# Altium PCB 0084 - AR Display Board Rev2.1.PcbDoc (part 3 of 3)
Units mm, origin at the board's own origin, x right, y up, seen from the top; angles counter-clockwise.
Board outline 127.7 x 27.2 mm, 4 copper layers (L1-TOP, L2-GND, L3-GND, L4-BOT), stack 1.571 mm thick; 141 components, 141 nets, 671 pads, 447 vias.
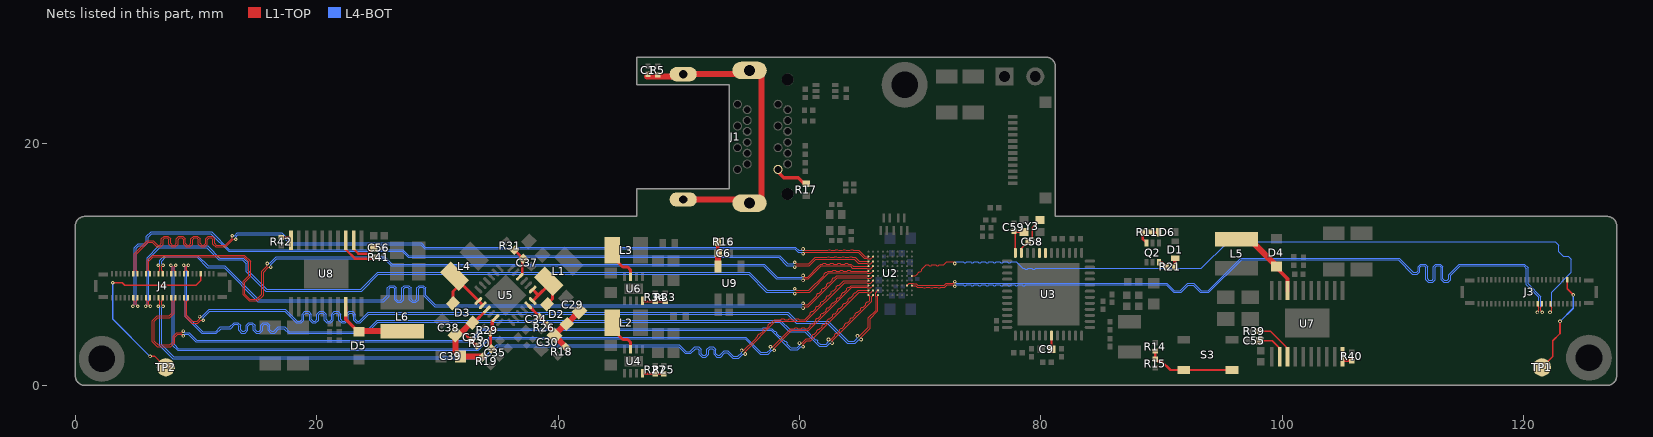
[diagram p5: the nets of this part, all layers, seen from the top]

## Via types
v1: diameter 0.3, hole 0.15, L1-TOP to L4-BOT, tented both sides, 445 vias
v2: diameter 0.25, hole 0.1, L1-TOP to L4-BOT, tented both sides, 2 vias

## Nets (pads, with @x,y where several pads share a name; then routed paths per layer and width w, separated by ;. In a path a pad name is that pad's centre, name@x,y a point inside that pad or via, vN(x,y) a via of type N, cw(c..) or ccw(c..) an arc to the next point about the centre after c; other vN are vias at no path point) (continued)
MIPI_DSI01_3_P: J3.35 U2.F10 | length 63.9
  L1-TOP w0.076: U2.F10@69.3,9.075 69.591,9.075 69.698,9.183 69.914,9.398 70.022,9.398 70.129,9.506 70.129,9.614 70.345,9.829 70.516,10 70.668,10 70.744,9.924 70.897,9.924 70.973,10 71.278,10 71.354,9.924 71.506,9.924 71.582,10 71.8,10 71.96,10 72.184,10.224 72.736,10.224 v1(72.86,10.1) ; v1@122.187,6.05 v1(122.175,6.05) 122.299,6.174 122.299,6.476 122.2,6.575 J3.35@122.2,6.75
  L4-BOT w0.076: v1(72.86,10.1) 72.984,10.224 73.1,10.224 73.252,10.224 73.557,10.224 73.633,10.148 73.786,10.148 73.862,10.224 74.167,10.224 74.243,10.148 74.395,10.148 74.472,10.224 74.776,10.224 74.853,10.148 75.005,10.148 75.081,10.224 75.386,10.224 75.462,10.148 75.615,10.148 75.691,10.224 75.996,10.224 76.072,10.148 76.224,10.148 76.3,10.224 76.605,10.224 76.681,10.148 76.834,10.148 76.91,10.224 77.215,10.224 77.291,10.148 77.443,10.148 77.52,10.224 77.824,10.224 77.961,10.224 78.484,9.7 78.637,9.7 78.713,9.624 78.865,9.624 78.942,9.7 79.246,9.7 79.323,9.624 79.475,9.624 79.551,9.7 79.6,9.7 93.3,9.7 95.5,11.9 122.6,11.9 122.9,11.6 122.9,11.084 123.284,10.7 123.684,10.7 123.948,10.437 123.948,9.376 122.299,7.727 122.299,6.174 v1(122.175,6.05)
MIPI_DSI01_C_N: J3.31 U2.H9 | length 64
  L1-TOP w0.076: U2.H9@68.9,8.275 69.1,8.475 69.383,8.475 69.43,8.427 69.673,8.427 69.8,8.3 71.984,8.3 72.161,8.476 72.736,8.476 v1(72.86,8.6) ; J3.31@121.5,6.75 121.5,6.575 121.401,6.476 121.401,6.174 v1(121.525,6.05) v1@121.513,6.05
  L4-BOT w0.076: v1(72.86,8.6) 72.984,8.476 90.439,8.476 91.063,7.852 91.552,7.852 92.152,8.452 92.663,8.452 93.263,7.852 93.852,7.852 96.552,10.552 109.663,10.552 ; 109.678,10.552 109.663,10.552 ; v1(121.525,6.05) 121.401,6.174 121.401,7.35 120.351,8.4 120.351,9.739 120.041,10.05 114.657,10.05 113.781,9.174 113.781,8.824 113.667,8.71 113.413,8.71 113.299,8.824 113.299,9.841 113.095,10.045 112.715,10.045 112.511,9.841 112.511,8.824 112.397,8.71 112.143,8.71 112.029,8.824 112.029,9.841 111.825,10.045 111.445,10.045 111.241,9.841 111.241,9.492 111.127,9.377 110.838,9.377 109.663,10.552
MIPI_DSI01_C_P: J3.29 U2.H10 | length 63.9
  L1-TOP w0.076: U2.H10@69.3,8.275 69.609,8.275 69.737,8.148 69.889,8.148 70.194,8.148 70.27,8.071 70.423,8.071 70.499,8.148 70.804,8.148 70.88,8.071 71.032,8.071 71.108,8.148 71.413,8.148 71.489,8.071 71.642,8.071 71.718,8.148 72.023,8.148 72.048,8.148 72.224,8.324 72.736,8.324 v1(72.86,8.2) ; v1@121.137,6.05 v1(121.125,6.05) 121.249,6.174 121.249,6.476 121.15,6.575 J3.29@121.15,6.75
  L4-BOT w0.076: v1(72.86,8.2) 72.984,8.324 73.1,8.324 73.252,8.324 73.557,8.324 73.633,8.248 73.786,8.248 73.862,8.324 74.167,8.324 74.243,8.248 74.395,8.248 74.472,8.324 74.776,8.324 74.853,8.248 75.005,8.248 75.081,8.324 75.386,8.324 75.462,8.248 75.615,8.248 75.691,8.324 75.996,8.324 76.072,8.248 76.224,8.248 76.3,8.324 76.605,8.324 76.681,8.248 76.834,8.248 76.91,8.324 77.215,8.324 77.291,8.248 77.443,8.248 77.52,8.324 77.824,8.324 77.901,8.248 78.053,8.248 78.129,8.324 78.434,8.324 78.51,8.248 78.663,8.248 78.739,8.324 90.376,8.324 91,7.7 91.616,7.7 92.216,8.3 92.6,8.3 93.2,7.7 93.916,7.7 96.616,10.4 109.6,10.4 110.775,9.225 111.19,9.225 111.394,9.428 111.394,9.778 111.508,9.892 111.762,9.892 111.876,9.778 111.876,8.761 112.08,8.558 112.46,8.558 112.664,8.761 112.664,9.778 112.778,9.892 113.032,9.892 113.146,9.778 113.146,8.761 113.35,8.558 113.73,8.558 113.934,8.761 113.934,9.111 114.72,9.898 119.977,9.898 120.199,9.676 120.199,8.337 121.249,7.287 121.249,6.174 v1(121.125,6.05)
MIPI_DSI10_0_N: J4.11 U2.C1 | length 69.1
  L1-TOP w0.076: v1@4.787,6.55 v1(4.775,6.55) 4.899,6.674 4.899,6.976 4.8,7.075 J4.11@4.8,7.25 ; v1(59.6,10.2) 59.724,10.076 60.761,10.076 61.284,10.6 62.1,10.6 62.252,10.6 62.329,10.676 62.481,10.676 62.557,10.6 62.862,10.6 62.938,10.676 63.091,10.676 63.167,10.6 63.472,10.6 63.548,10.676 63.7,10.676 63.776,10.6 64.081,10.6 64.157,10.676 64.31,10.676 64.386,10.6 64.616,10.6 64.941,10.275 U2.C1@65.7,10.275
  L4-BOT w0.076: v1(4.775,6.55) 4.899,6.674 4.899,11.414 5.212,11.727 5.712,11.727 5.898,11.913 5.898,12.338 6.287,12.727 11.288,12.727 12.763,11.252 27.138,11.252 27.638,10.752 58.348,10.752 59.024,10.076 59.476,10.076 v1(59.6,10.2)
MIPI_DSI10_0_P: J4.13 U2.C2 | length 69.1
  L1-TOP w0.076: J4.13@5.15,7.25 5.15,7.075 5.051,6.976 5.051,6.674 v1(5.175,6.55) v1@5.163,6.55 ; v1(59.6,9.8) 59.724,9.924 60.824,9.924 61.348,10.448 64.552,10.448 64.877,10.123 65.57,10.123 65.617,10.075 65.9,10.075 U2.C2@66.1,10.275
  L4-BOT w0.076: v1(5.175,6.55) 5.051,6.674 5.051,11.351 5.275,11.575 5.775,11.575 6.05,11.85 6.05,12.275 6.35,12.575 11.225,12.575 12.7,11.1 27.075,11.1 27.575,10.6 58.284,10.6 58.961,9.924 59.476,9.924 v1(59.6,9.8)
MIPI_DSI10_1_N: J4.17 U2.E1 | length 69.1
  L1-TOP w0.076: v1@5.837,6.55 v1(5.825,6.55) 5.949,6.674 5.949,6.976 5.85,7.075 J4.17@5.85,7.25 ; v1(59.6,8) 59.724,7.876 60.776,7.876 62,9.1 62.052,9.152 62.052,9.259 62.159,9.367 62.267,9.367 62.375,9.475 62.414,9.475 62.719,9.475 62.795,9.551 62.947,9.551 63.024,9.475 63.328,9.475 63.405,9.551 63.557,9.551 63.633,9.475 63.938,9.475 64.014,9.551 64.167,9.551 64.243,9.475 64.548,9.475 64.7,9.475 U2.E1@65.7,9.475
  L4-BOT w0.076: v1(5.825,6.55) 5.949,6.674 5.949,10.564 6.937,11.552 10.963,11.552 11.963,10.552 13.913,10.552 14.325,10.141 14.325,9.491 15.863,7.952 23.652,7.952 25.052,9.352 55.848,9.352 57.324,7.876 59.476,7.876 v1(59.6,8)
MIPI_DSI10_1_P: J4.19 U2.E2 | length 69.1
  L1-TOP w0.076: J4.19@6.2,7.25 6.2,7.075 6.101,6.976 6.101,6.674 v1(6.225,6.55) v1@6.213,6.55 ; v1(59.6,7.6) 59.724,7.724 60.839,7.724 62.438,9.323 65.57,9.323 65.617,9.275 65.9,9.275 U2.E2@66.1,9.475
  L4-BOT w0.076: v1(6.225,6.55) 6.101,6.674 6.101,10.501 7,11.4 10.9,11.4 11.9,10.4 13.85,10.4 14.173,10.077 14.173,9.427 15.8,7.8 23.716,7.8 25.116,9.2 55.784,9.2 57.261,7.724 59.476,7.724 v1(59.6,7.6)
MIPI_DSI10_2_N: J4.24 U2.F1 | length 69.1
  L1-TOP w0.076: v1@6.887,9.95 v1(6.875,9.95) 6.999,9.826 6.999,9.524 6.9,9.425 J4.24@6.9,9.25 ; v1(60.3,6.8) 60.424,6.676 60.676,6.676 61.3,7.3 61.408,7.408 61.408,7.516 61.516,7.623 61.623,7.623 61.839,7.839 61.839,7.947 61.947,8.054 62.054,8.054 62.27,8.27 62.27,8.378 62.378,8.485 62.485,8.485 62.701,8.701 62.701,8.809 62.809,8.916 62.916,8.916 63,9 63.075,9.075 U2.F1@65.7,9.075
  L4-BOT w0.076: v1(6.875,9.95) 6.999,10.074 6.999,10.363 7.436,10.8 10.116,10.8 11.016,9.9 12.4,9.9 15.2,7.1 25.485,7.1 25.848,7.462 25.848,8.073 26.049,8.275 26.408,8.275 26.61,8.073 26.61,7.14 26.725,7.025 26.933,7.025 27.067,7.159 27.067,8.073 27.269,8.275 27.627,8.275 27.829,8.073 27.829,7.167 27.971,7.025 28.152,7.025 28.286,7.159 28.286,8.073 28.488,8.275 28.847,8.275 29.048,8.073 29.048,7.462 29.834,6.676 60.176,6.676 v1(60.3,6.8)
MIPI_DSI10_2_P: J4.26 U2.F2 | length 69.1
  L1-TOP w0.076: J4.26@7.25,9.25 7.25,9.425 7.151,9.524 7.151,9.826 v1(7.275,9.95) v1@7.263,9.95 ; v1(60.3,6.4) 60.424,6.524 60.739,6.524 63.138,8.923 65.57,8.923 65.617,8.875 65.9,8.875 U2.F2@66.1,9.075
  L4-BOT w0.076: v1(7.275,9.95) 7.151,10.074 7.151,10.3 7.499,10.648 10.052,10.648 10.952,9.748 12.337,9.748 15.137,6.948 25.549,6.948 26,7.399 26,8.01 26.113,8.123 26.345,8.123 26.457,8.01 26.457,7.077 26.662,6.872 26.996,6.872 27.219,7.096 27.219,8.01 27.332,8.123 27.564,8.123 27.677,8.01 27.677,7.104 27.908,6.872 28.215,6.872 28.439,7.096 28.439,8.01 28.551,8.123 28.783,8.123 28.896,8.01 28.896,7.399 29.771,6.524 60.176,6.524 v1(60.3,6.4)
MIPI_DSI10_3_N: J4.12 U2.B1 | length 69.1
  L1-TOP w0.076: J4.12@4.8,9.25 4.8,9.425 4.899,9.524 4.899,10.914 5.984,12 6.447,12 6.823,11.624 7.004,11.624 7.142,11.762 7.142,12.148 7.37,12.376 7.677,12.376 7.904,12.148 7.904,11.762 8.042,11.624 8.223,11.624 8.361,11.762 8.361,12.148 8.589,12.376 8.896,12.376 9.123,12.148 9.123,11.762 9.262,11.624 9.442,11.624 9.581,11.762 9.581,12.148 9.808,12.376 10.115,12.376 10.343,12.148 10.343,11.762 10.481,11.624 10.662,11.624 10.8,11.762 10.8,12.148 11.027,12.376 11.334,12.376 11.562,12.148 11.562,11.762 11.7,11.624 12.416,11.624 13,12.208 v1(13,12.4) ; v1(60.3,11.3) 60.424,11.176 62.1,11.176 62.333,11.176 62.409,11.252 62.562,11.252 62.638,11.176 62.943,11.176 63.019,11.252 63.171,11.252 63.247,11.176 63.552,11.176 63.628,11.252 63.781,11.252 63.857,11.176 64.162,11.176 64.238,11.252 64.39,11.252 64.467,11.176 64.771,11.176 64.924,11.176 65.425,10.675 U2.B1@65.7,10.675
  L4-BOT w0.076: v1(13,12.4) 13.192,12.4 13.417,12.625 17.091,12.625 17.916,11.8 28.666,11.8 29.013,11.452 59.663,11.452 59.939,11.176 60.176,11.176 v1(60.3,11.3)
MIPI_DSI10_3_P: J4.14 U2.B2 | length 69.1
  L1-TOP w0.076: J4.14@5.15,9.25 5.15,9.425 5.051,9.524 5.051,10.851 6.048,11.848 6.384,11.848 6.76,11.472 7.067,11.472 7.295,11.699 7.295,12.085 7.433,12.224 7.614,12.224 7.752,12.085 7.752,11.699 7.979,11.472 8.286,11.472 8.514,11.699 8.514,12.085 8.652,12.224 8.833,12.224 8.971,12.085 8.971,11.699 9.199,11.472 9.505,11.472 9.733,11.699 9.733,12.085 9.871,12.224 10.052,12.224 10.19,12.085 10.19,11.699 10.418,11.472 10.725,11.472 10.952,11.699 10.952,12.085 11.09,12.224 11.271,12.224 11.409,12.085 11.409,11.699 11.637,11.472 12.479,11.472 13.108,12.1 v1(13.3,12.1) ; v1(60.3,10.9) 60.424,11.024 64.861,11.024 65.362,10.523 65.57,10.523 65.617,10.475 65.9,10.475 U2.B2@66.1,10.675
  L4-BOT w0.076: v1(13.3,12.1) 13.3,12.292 13.48,12.473 17.027,12.473 17.852,11.648 28.602,11.648 28.95,11.3 59.6,11.3 59.876,11.024 60.176,11.024 v1(60.3,10.9)
MIPI_DSI10_C_N: J4.18 U2.D1 | length 69.1
  L1-TOP w0.076: J4.18@5.85,9.25 5.85,9.425 5.949,9.524 5.949,10.349 6.4,10.8 14.016,10.8 14.525,10.291 14.525,9.025 14.052,8.552 14.052,7.563 14.463,7.152 15.052,7.152 15.448,7.548 15.448,9.455 15.9,9.908 v1(15.9,10.1) ; v1(60.3,9.1) 60.424,8.976 60.676,8.976 61.6,9.9 61.708,10.008 61.752,10.052 61.905,10.052 61.981,10.129 62.133,10.129 62.21,10.052 62.514,10.052 62.591,10.129 62.743,10.129 62.819,10.052 63.124,10.052 63.2,10.129 63.353,10.129 63.429,10.052 63.734,10.052 63.81,10.129 63.962,10.129 64.038,10.052 64.2,10.052 64.263,10.052 64.441,9.875 U2.D1@65.7,9.875
  L4-BOT w0.076: v1(15.9,10.1) 16.092,10.1 16.645,10.652 25.648,10.652 26.248,10.052 57.063,10.052 58.139,8.976 60.176,8.976 v1(60.3,9.1)
MIPI_DSI10_C_P: J4.20 U2.D2 | length 69.1
  L1-TOP w0.076: J4.20@6.2,9.25 6.2,9.425 6.101,9.524 6.101,10.286 6.463,10.648 13.952,10.648 14.373,10.227 14.373,9.088 13.9,8.616 13.9,7.5 14.4,7 15.116,7 15.6,7.484 15.6,9.392 16.008,9.8 v1(16.2,9.8) ; v1(60.3,8.7) 60.424,8.824 60.739,8.824 61.816,9.9 64.2,9.9 64.377,9.723 65.57,9.723 65.617,9.675 65.9,9.675 U2.D2@66.1,9.875
  L4-BOT w0.076: v1(16.2,9.8) 16.2,9.992 16.708,10.5 25.584,10.5 26.184,9.9 57,9.9 58.076,8.824 60.176,8.824 v1(60.3,8.7)
MIPI_DSI11_0_N: J4.38 U2.K1 | length 69.1
  L1-TOP w0.076: J4.38@9.35,9.25 9.35,9.425 9.251,9.524 9.251,9.826 v1(9.375,9.95) v1@9.363,9.95 ; v1(62.4,3.8) 62.592,3.8 62.792,4 62.9,4.108 62.9,4.216 63.008,4.323 63.116,4.323 63.331,4.539 63.331,4.647 63.439,4.754 63.547,4.754 63.762,4.97 63.762,5.078 63.87,5.185 63.978,5.185 64.193,5.401 64.193,5.509 64.301,5.616 64.409,5.616 64.624,5.832 64.624,5.94 64.732,6.047 64.84,6.047 65.055,6.263 65.055,6.371 65.163,6.479 65.271,6.479 65.486,6.694 65.486,6.802 65.594,6.91 65.702,6.91 65.8,7.008 65.824,7.032 65.824,7.351 U2.K1@65.7,7.475
  L4-BOT w0.076: v1(9.375,9.95) 9.251,9.826 9.251,5.749 10.548,4.452 11.637,4.452 12.029,4.845 12.8,4.845 13.156,5.201 13.463,5.201 13.691,4.973 13.691,4.627 13.829,4.488 14.01,4.488 14.148,4.627 14.148,4.973 14.375,5.201 14.682,5.201 14.91,4.973 14.91,4.627 15.048,4.488 15.229,4.488 15.367,4.627 15.367,4.973 15.595,5.201 15.901,5.201 16.129,4.973 16.129,4.627 16.267,4.488 16.448,4.488 16.804,4.845 17.355,4.845 17.748,4.452 24.052,4.452 25,5.4 58.416,5.4 59.216,4.6 60.5,4.6 61.308,3.792 61.416,3.792 61.523,3.684 61.523,3.577 61.696,3.404 62.196,3.404 62.4,3.608 v1(62.4,3.8)
MIPI_DSI11_0_P: J4.36 U2.K2 | length 69.1
  L1-TOP w0.076: v1@8.987,9.95 v1(8.975,9.95) 9.099,9.826 9.099,9.524 9,9.425 J4.36@9,9.25 ; v1(62.7,3.5) 62.7,3.692 65.976,6.968 65.976,7.351 U2.K2@66.1,7.475
  L4-BOT w0.076: v1(8.975,9.95) 9.099,9.826 9.099,5.686 10.484,4.3 11.7,4.3 12.092,4.692 12.863,4.692 13.219,5.049 13.4,5.049 13.538,4.91 13.538,4.563 13.766,4.336 14.073,4.336 14.3,4.563 14.3,4.91 14.438,5.049 14.619,5.049 14.757,4.91 14.757,4.563 14.985,4.336 15.292,4.336 15.519,4.563 15.519,4.91 15.658,5.049 15.838,5.049 15.977,4.91 15.977,4.563 16.204,4.336 16.511,4.336 16.867,4.692 17.292,4.692 17.684,4.3 24.116,4.3 25.063,5.248 58.352,5.248 59.152,4.448 60.437,4.448 61.633,3.251 62.259,3.251 62.508,3.5 v1(62.7,3.5)
MIPI_DSI11_1_N: J4.32 U2.H1 | length 69.1
  L1-TOP w0.076: J4.32@8.3,9.25 8.3,9.425 8.201,9.524 8.201,9.826 v1(8.325,9.95) v1@8.313,9.95 ; v1(57.6,3.2) 57.792,3.2 59.292,4.7 59.4,4.7 59.552,4.7 59.629,4.776 59.781,4.776 59.857,4.7 60.162,4.7 60.238,4.776 60.391,4.776 60.467,4.7 60.6,4.7 60.7,4.7 60.8,4.8 60.908,4.908 60.908,5.016 61.016,5.123 61.123,5.123 61.339,5.339 61.339,5.447 61.447,5.554 61.554,5.554 61.77,5.77 61.77,5.878 61.878,5.985 61.985,5.985 62.201,6.201 62.201,6.309 62.309,6.416 62.416,6.416 62.632,6.632 62.632,6.74 62.74,6.847 62.847,6.847 63.063,7.063 63.063,7.171 63.171,7.279 63.279,7.279 63.494,7.494 63.494,7.602 63.602,7.71 63.71,7.71 63.925,7.925 63.925,8.033 64.033,8.141 64.141,8.141 64.275,8.275 64.427,8.275 ; 64.3,8.275 64.427,8.275 ; U2.H1@65.7,8.275 64.427,8.275
  L4-BOT w0.076: v1(8.325,9.95) 8.201,9.826 8.201,9.537 8.2,9.536 8.2,3.4 8.548,3.052 33.337,3.052 34.284,4 55.55,4 56.8,2.75 57.342,2.75 57.6,3.008 v1(57.6,3.2)
MIPI_DSI11_1_P: J4.30 U2.H2 | length 69.1
  L1-TOP w0.076: v1@7.937,9.95 v1(7.925,9.95) 8.049,9.826 8.049,9.524 7.95,9.425 J4.30@7.95,9.25 ; v1(57.9,2.9) 57.9,3.092 59.355,4.548 60.763,4.548 64.338,8.123 65.57,8.123 65.617,8.075 65.9,8.075 U2.H2@66.1,8.275
  L4-BOT w0.076: v1(7.925,9.95) 8.049,9.826 8.049,9.6 8.048,9.599 8.048,3.337 8.484,2.9 33.4,2.9 34.348,3.848 55.487,3.848 56.737,2.598 57.405,2.598 57.708,2.9 v1(57.9,2.9)
MIPI_DSI11_2_N: J4.25 U2.G1 | length 69.1
  L1-TOP w0.076: J4.25@7.25,7.25 7.25,7.075 7.151,6.976 7.151,6.674 v1(7.275,6.55) v1@7.263,6.55 ; v1(55.2,2.9) 55.392,2.9 56.292,3.8 56.544,4.051 56.544,4.159 56.651,4.267 56.759,4.267 56.975,4.483 56.975,4.59 57.083,4.698 57.19,4.698 57.406,4.914 57.406,5.021 57.514,5.129 57.621,5.129 57.837,5.345 57.945,5.452 58.3,5.452 58.452,5.452 58.529,5.529 58.681,5.529 58.757,5.452 59.062,5.452 59.138,5.529 59.291,5.529 59.367,5.452 59.672,5.452 59.748,5.529 59.9,5.529 59.976,5.452 60.2,5.452 60.452,5.452 60.7,5.7 60.906,5.906 60.906,6.014 61.014,6.121 61.121,6.121 61.337,6.337 61.337,6.445 61.445,6.552 61.553,6.552 61.768,6.768 61.768,6.876 61.876,6.984 61.984,6.984 62.199,7.199 62.199,7.307 62.307,7.415 62.415,7.415 62.63,7.63 62.63,7.738 62.738,7.846 62.846,7.846 63.061,8.061 63.061,8.169 63.169,8.277 63.277,8.277 63.492,8.492 63.6,8.6 63.675,8.675 U2.G1@65.7,8.675
  L4-BOT w0.076: v1(7.275,6.55) 7.151,6.426 7.151,3.349 8.148,2.352 33.937,2.352 34.937,3.352 50.048,3.352 50.6,2.8 50.918,2.8 51.325,3.207 51.632,3.207 51.86,2.979 51.86,2.636 51.998,2.498 52.179,2.498 52.317,2.636 52.317,2.979 52.545,3.207 52.852,3.207 53.079,2.979 53.079,2.636 53.217,2.498 53.398,2.498 53.753,2.852 54.063,2.852 54.516,2.4 54.892,2.4 55.2,2.708 v1(55.2,2.9)
MIPI_DSI11_2_P: J4.23 U2.G2 | length 69.1
  L1-TOP w0.076: v1@6.887,6.55 v1(6.875,6.55) 6.999,6.674 6.999,6.976 6.9,7.075 J4.23@6.9,7.25 ; v1(55.5,2.6) 55.5,2.792 58.008,5.3 60.516,5.3 63.738,8.523 65.57,8.523 65.617,8.475 65.9,8.475 U2.G2@66.1,8.675
  L4-BOT w0.076: v1(6.875,6.55) 6.999,6.426 6.999,3.286 8.084,2.2 34,2.2 35,3.2 49.984,3.2 50.537,2.648 50.982,2.648 51.389,3.055 51.569,3.055 51.707,2.916 51.707,2.573 51.935,2.345 52.242,2.345 52.469,2.573 52.469,2.916 52.608,3.055 52.788,3.055 52.927,2.916 52.927,2.573 53.154,2.345 53.461,2.345 53.816,2.7 54,2.7 54.452,2.248 54.955,2.248 55.308,2.6 v1(55.5,2.6)
MIPI_DSI11_3_N: J4.37 U2.J3 | length 69.1
  L1-TOP w0.076: J4.37@9.35,7.25 9.35,7.075 9.251,6.976 9.251,5.749 9.7,5.3 10.092,5.3 10.3,5.508 v1(10.3,5.7) ; v1(64.8,4.1) 64.992,4.1 65.696,4.804 65.696,5.596 66.344,6.244 66.344,7.348 66.3,7.392 66.3,7.675 U2.J3@66.5,7.875
  L4-BOT w0.076: v1(10.3,5.7) 10.492,5.7 11.092,6.3 17.4,6.3 18.374,5.326 18.658,5.326 18.796,5.464 18.796,5.897 19.024,6.124 19.331,6.124 19.558,5.897 19.558,5.464 19.697,5.326 19.877,5.326 20.016,5.464 20.016,5.897 20.243,6.124 20.55,6.124 20.778,5.897 20.778,5.464 20.916,5.326 21.096,5.326 21.235,5.464 21.235,5.897 21.462,6.124 21.769,6.124 21.997,5.897 21.997,5.464 22.135,5.326 22.316,5.326 22.454,5.464 22.454,5.897 22.681,6.124 22.988,6.124 23.216,5.897 23.216,5.464 23.354,5.326 23.535,5.326 24.262,6.052 59.048,6.052 59.8,5.3 62.375,5.3 64.025,3.65 64.542,3.65 64.8,3.908 v1(64.8,4.1)
MIPI_DSI11_3_P: J4.35 U2.K3 | length 69.1
  L1-TOP w0.076: J4.35@9,7.25 9,7.075 9.099,6.976 9.099,5.686 9.637,5.148 10.155,5.148 10.408,5.4 v1(10.6,5.4) ; v1(65.1,3.8) 65.1,3.992 65.849,4.741 65.849,5.533 66.5,6.184 U2.K3@66.5,7.475
  L4-BOT w0.076: v1(10.6,5.4) 10.6,5.592 11.155,6.148 17.337,6.148 18.311,5.173 18.721,5.173 18.949,5.401 18.949,5.834 19.087,5.972 19.268,5.972 19.406,5.834 19.406,5.401 19.633,5.173 19.94,5.173 20.168,5.401 20.168,5.834 20.306,5.972 20.487,5.972 20.625,5.834 20.625,5.401 20.853,5.173 21.16,5.173 21.387,5.401 21.387,5.834 21.525,5.972 21.706,5.972 21.844,5.834 21.844,5.401 22.072,5.173 22.379,5.173 22.606,5.401 22.606,5.834 22.745,5.972 22.925,5.972 23.064,5.834 23.064,5.401 23.291,5.173 23.598,5.173 24.325,5.9 58.984,5.9 59.737,5.148 62.312,5.148 63.962,3.498 64.605,3.498 64.908,3.8 v1(65.1,3.8)
MIPI_DSI11_C_N: J4.31 U2.J1 | length 69.1
  L1-TOP w0.076: J4.31@8.3,7.25 8.3,7.075 8.201,6.976 8.201,5.961 7.841,5.6 6.85,5.6 6.55,5.3 6.55,3.666 6.863,3.352 7.837,3.352 8.1,3.616 8.1,4.063 8.413,4.376 8.826,4.376 v1(8.95,4.5) ; v1(60,3.5) 60.192,3.5 60.545,3.852 60.852,3.852 60.9,3.9 61.008,4.008 61.008,4.108 61.123,4.223 61.223,4.223 61.439,4.439 61.439,4.539 61.554,4.654 61.654,4.654 61.87,4.87 61.87,4.97 61.985,5.085 62.085,5.085 62.301,5.301 62.301,5.401 62.416,5.516 62.516,5.516 62.732,5.732 62.732,5.833 62.847,5.947 62.947,5.947 63.163,6.163 63.163,6.264 63.278,6.379 63.379,6.379 63.594,6.594 63.594,6.695 63.709,6.81 63.81,6.81 64.025,7.025 64.025,7.126 64.14,7.241 64.241,7.241 64.456,7.456 64.456,7.557 64.571,7.672 64.672,7.672 64.8,7.8 64.875,7.875 U2.J1@65.7,7.875
  L4-BOT w0.076: v1(8.95,4.5) 9.074,4.376 9.424,4.376 10.048,3.752 32.721,3.752 33.669,4.7 56.938,4.7 57.006,4.768 57.175,4.768 57.243,4.7 57.548,4.7 57.7,4.7 57.895,4.505 57.991,4.505 58.111,4.386 58.111,4.289 58.326,4.074 58.423,4.074 58.542,3.954 58.542,3.858 58.757,3.643 58.854,3.643 58.973,3.523 58.973,3.427 59.188,3.212 59.296,3.104 59.796,3.104 60,3.308 v1(60,3.5)
MIPI_DSI11_C_P: J4.29 U2.J2 | length 69.1
  L1-TOP w0.076: J4.29@7.95,7.25 7.95,7.075 8.049,6.976 8.049,6.024 7.777,5.752 6.787,5.752 6.398,5.363 6.398,3.602 6.8,3.2 7.9,3.2 8.252,3.552 8.252,4 8.476,4.224 8.826,4.224 v1(8.95,4.1) ; v1(60.3,3.2) 60.3,3.392 60.608,3.7 60.916,3.7 64.938,7.723 65.57,7.723 65.617,7.675 65.9,7.675 U2.J2@66.1,7.875
  L4-BOT w0.076: v1(8.95,4.1) 9.074,4.224 9.361,4.224 9.984,3.6 32.784,3.6 33.732,4.548 57.637,4.548 59.233,2.951 59.859,2.951 60.108,3.2 v1(60.3,3.2)
NetC1_2: C1.2 J1.0 R5.2 | length 27.3
  L1-TOP w0.5: C1.2@47.36,25.6 50.175,25.6 J1.0@50.365,25.79 55.565,25.79 J1.0@55.865,26.09 56.86,26.09 56.86,15.1 J1.0@55.865,15.1 55.565,15.4 J1.0@50.365,15.4
NetC6_1: C6.1 R16.1 U9.5 | length 2.2
  L1-TOP w0.3: R16.1@53.225,11.89 53.225,10.95 C6.1@53.25,10.925 ; C6.1@53.275,10.95 C6.1@53.325,11
  L1-TOP w0.5: U9.5@53.25,9.85 53.25,10.925 C6.1@53.275,10.95
NetC35_1: C35.1 R29.1 U5.17 | length 2.8
  L1-TOP w0.25: R29.1@34.35,4.425 34.544,4.619 34.544,5.306 U5.17@34.813,5.575 ; R29.1@34.444,4.372 R29.1@34.392,4.319 34.4,4.311 34.4,3.1 C35.1@34.482,3.018
NetC37_2: C37.2 R31.2 U5.4 | length 2.7
  L1-TOP w0.1: C37.2@37.126,10.485 C37.2@37.144,10.467
  L1-TOP w0.2: R31.2@36.398,11.213 C37.2@37.126,10.485 37.044,10.403 37.044,9.22 U5.4@36.829,9.004
NetC55_1: C55.1 U7.2 | length 3.5
  L1-TOP w0.15: C55.1@98.11,3.5 C55.1@98.21,3.6 ; C55.1@98.11,3.7 99.16,3.7 U7.2@99.779,3.081 ; U7.2@99.779,3.081 U7.2@99.779,2.365 U7.2@99.779,3.081
NetC56_1: C56.1 U8.2 | length 2.7
  L1-TOP w0.2: U8.2@23.068,12.016 23.068,11.292 23.46,10.9 24.21,10.9 C56.1@24.71,11.4
NetC58_1: C58.1 U3.23 Y3.3 | length 3.4
  L1-TOP w0.127: U3.23@78.375,10.975 78.375,11.345 C58.1@78.93,11.9 79.26,12.23 79.26,13.05 Y3.3@79.91,13.7
NetC59_1: C59.1 U3.24 Y3.1 | length 2.7
  L1-TOP w0.1: C59.1@77.76,12.77 77.83,12.7 C59.1@77.875,12.655 ; Y3.1@78.54,12.77 Y3.1@78.61,12.7
  L1-TOP w0.127: C59.1@77.83,12.7 Y3.1@78.61,12.7 ; U3.24@77.875,10.975 C59.1@77.875,12.655
NetD1_K: D1.K R21.1 | length 0.7
  L1-TOP w0.3: R21.1@91.075,9.825 D1.K@91.075,10.525
NetD2_A: D2.A L1.2 U5.1 U5.24 | length 5.5
  L1-TOP w0.1: L1.2@39.22,8.32 L1.2@39.22,8.643 L1.2@39.544,8.319 ; L1.2@39.644,8.219 L1.2@39.944,7.919
  L1-TOP w0.25: U5.24@37.889,6.989 38.367,7.467 ; U5.1@37.889,7.944 38.367,7.467 ; D2.A@39.144,6.767 39.544,7.167 L1.2@39.544,8.319 ; L1.2@39.22,8.32 38.367,7.467
NetD3_K: D3.K L4.1 U5.13 U5.14 | length 6.5
  L1-TOP w0.25: D3.K@31.144,6.875 D3.K@31.366,6.653 ; D3.K@31.287,6.813 31.287,7.787 31.944,8.444 L4.1@31.844,8.544 ; L4.1@31.383,9.005 L4.1@31.844,8.544 ; L4.1@31.42,8.99 L4.1@31.844,8.567 ; L4.1@31.844,8.467 L4.1@31.844,8.544 ; L4.1@31.844,8.619 L4.1@31.844,8.567 ; U5.14@33.753,6.636 33.753,6.658 L4.1@31.844,8.567 ; L4.1@31.844,8.544 L4.1@31.844,8.567
  L1-TOP w0.5: L4.1@31.42,8.99 L4.1@31.42,9.043
NetD6_K: D6.K R11.1 | length 0.6
  L1-TOP w0.15: R11.1@89.15,12.675 D6.K@89.75,12.675
NetJ1_20: J1.20 R17.1 | length 2.8
  L1-TOP w0.3: J1.20@58.215,17.69 58.705,17.2 59.9,17.2 60.4,16.7 R17.1@60.56,16.7
NetL2_1: L2.1 U4.7 | length 3.8
  L1-TOP w0.1: L2.1@44.295,4.71 L2.1@44.295,5.2
  L1-TOP w0.25: L2.1@44.195,5.2 44.295,5.2 44.395,5.2 44.395,4.765 45.36,3.8 45.76,3.8 46.01,3.55 U4.7@46.01,2.995
NetL3_1: L3.1 U6.7 | length 3.1
  L1-TOP w0.25: L3.1@44.495,11.2 44.495,10.665 45.36,9.8 45.76,9.8 46.01,9.55 U6.7@46.01,8.995
NetQ2_3: Q2.3 R11.2 | length 1
  L1-TOP w0.2: R11.2@88.45,12.675 88.45,12.11 Q2.3@88.76,11.8
NetQ2_6: Q2.6 R21.2 | length 0.8
  L1-TOP w0.2: Q2.6@89.76,10.175 90.025,10.175 R21.2@90.375,9.825
NetR14_1: R14.1 R15.1 S3.2 | length 7.4
  L1-TOP w0.2: R14.1@89.46,2.85 R15.1@89.46,2.15 89.51,2.15 89.66,2 90,2 90.725,1.275 S3.2@91.825,1.275 S3.2@95.825,1.275
NetR25_1: R25.1 R27.2 U4.4 | length 1.9
  L1-TOP w0.1: U4.4@47.01,0.9 U4.4@47.01,1.005
  L1-TOP w0.2: U4.4@47.01,1.005 47.065,0.95 R27.2@48.06,0.95 R25.1@48.76,0.95
NetR33_1: R33.1 R34.2 U6.4 | length 1.9
  L1-TOP w0.2: U6.4@47.01,6.95 R34.2@48.06,6.95 R33.1@48.86,6.95
  L1-TOP w0.25: U6.4@47.01,6.95 U6.4@47.01,7.005
NetR39_2: R39.2 U7.3 | length 5
  L1-TOP w0.125: U7.3@100.429,1.704 U7.3@100.429,2.365
  L1-TOP w0.127: R39.2@98.01,4.5 99,4.5 100.429,3.071 U7.3@100.429,2.365 U7.3@100.429,3.031
NetR40_2: R40.2 U7.10 | length 1.8
  L1-TOP w0.1: U7.10@104.979,2.365 U7.10@104.979,3.021
  L1-TOP w0.2: U7.10@104.979,2.365 104.979,2.05 R40.2@105.76,2.05 ; U7.10@104.979,3.021 U7.10@105.008,3.05
NetR41_2: R41.2 U8.3 | length 3.5
  L1-TOP w0.2: U8.3@22.418,12.016 22.418,11.242 23.16,10.5 24.71,10.5 R41.2@24.81,10.6
NetR42_2: R42.2 U8.10 | length 1.6
  L1-TOP w0.2: R42.2@17.06,12.25 U8.10@17.868,12.25 ; U8.10@17.818,12.2 U8.10@17.868,12.25 ; U8.10@17.868,12.016 U8.10@17.868,12.25 ; U8.10@17.868,12.7 U8.10@17.868,12.25
PB10: U3.19
PB11: U3.20
SW_L: D4.A L5.2 U7.18 | length 6.6
  L1-TOP w0.3: D4.A@99.5,9.9 99.5,9.76 100.429,8.831 U7.18@100.429,7.865
  L1-TOP w0.5: L5.2@96.2,12.1 97.3,12.1 D4.A@99.5,9.9
SW_R: D5.A L6.2 U8.18 | length 6.4
  L1-TOP w0.3: U8.18@22.418,6.516 22.418,5.482 23.45,4.45 D5.A@23.5,4.45
  L1-TOP w0.5: D5.A@23.5,4.45 23.5,4.5 L6.2@27.1,4.5 L6.2@27.1,4.25
TE_L: J3.44 TP1.0 | length 8.5
  L1-TOP w0.127: TP1.0@121.5,1.5 122.4,2.4 122.4,3.7 123,4.3 v1(123,5.3) ; J3.44@123.6,8.75 123.6,8 v1(124.1,7.5)
  L4-BOT w0.127: v1(123,5.3) 124.1,6.4 v1(124.1,7.5)
TE_R: J4.44 TP2.0 | length 17.9
  L1-TOP w0.127: v1(3.1,8.5) 3.9,8.5 4.1,8.3 10,8.3 10.4,8.7 J4.44@10.4,9.25 ; v1(6.2,2.4) 6.6,2.4 TP2.0@7.5,1.5 ; TP2.0@7.3,2 TP2.0@7.8,1.5
  L4-BOT w0.127: v1(3.1,8.5) 3.1,5.5 v1(6.2,2.4)
VDDCORE: C9.1 U3.43 | length 1.3
  L1-TOP w0.2: C9.1@80.875,2.85 U3.43@80.875,4.125
VNEG: C36.1 C38.2 C39.2 D3.A R19.1 R30.1 U5.15 | length 8.6
  L1-TOP w0.25: C38.2@31.933,4.333 32.2,4.333 C36.1@32.767,3.767 32.767,3.738 R30.1@33.253,3.253 ; D3.A@32.962,5.138 U5.15@34.106,6.282
  L1-TOP w0.5: C38.2@31.457,4.201 C38.2@31.51,4.201 31.51,2.79 C39.2@31.9,2.4 33.7,2.4 R19.1@33.746,2.354 ; C38.2@31.933,4.333 32.787,5.187 D3.A@32.913,5.187
VPOS: C29.2 C30.2 C34.1 D2.K R18.1 R26.1 U5.23 | length 7.7
  L1-TOP w0.1: C34.1@38.423,5.72 C34.1@38.423,5.748 ; R26.1@39.092,5.014 R26.1@39.092,5.051
  L1-TOP w0.25: U5.23@37.536,6.636 C34.1@38.423,5.748 ; C34.1@38.423,5.72 R26.1@39.092,5.051 ; R26.1@39.092,5.014 39.71,4.396 39.71,4.189 C30.2@39.71,4.132
  L1-TOP w0.5: C30.2@39.71,4.132 39.71,4.097 R18.1@40.654,3.154 ; C30.2@39.71,4.189 40.716,5.195 D2.K@40.716,5.241 ; D2.K@40.713,5.087 40.718,5.087 C29.2@41.766,6.134
pads on no net: J1. J2.0 Q1.1 Q1.2 Q1.6 U2.A3 U2.E9 U3.3 U3.13 U3.15 U3.16 U3.21 U3.22 U3.29 U3.33 U3.34 U3.39 U3.41 U3.47 U3.48 U4.6 U5.7 U5.12 U5.20 U6.6 U7.8 U7.19 U8.8 U8.19 U9.4

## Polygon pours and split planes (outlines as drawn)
5V on L4-BOT "BOT-5V" (solid, pour order 10): 80.8,26.6 80.8,15.6 67.4,15.6 67.4,15.9 70.9,19.4 70.9,26.6 71.2,26.9 80.5,26.9
GND on L2-GND (split plane): 80.498,26.89 80.591,26.862 80.678,26.816 80.753,26.753 80.816,26.678 80.862,26.591 80.89,26.498 80.899,26.407 80.899,26.4 80.899,14 80.904,13.941 80.921,13.885 80.949,13.833 80.987,13.787 81.033,13.749 81.085,13.722 81.141,13.704 81.2,13.699 126.9,13.699 126.907,13.699 126.998,13.69 127.091,13.662 127.178,13.616 127.253,13.553 127.316,13.478 127.362,13.391 127.39,13.298 127.399,13.207 127.399,13.2 127.399,0.8 127.399,0.793 127.39,0.703 127.362,0.609 127.316,0.522 127.253,0.447 127.178,0.384 127.091,0.338 126.998,0.31 126.907,0.301 126.9,0.301 0.8,0.301 0.793,0.301 0.702,0.31 0.609,0.338 0.522,0.384 0.447,0.447 0.384,0.522 0.338,0.609 0.31,0.702 0.301,0.793 0.301,0.8 0.301,13.2 0.301,13.207 0.31,13.298 0.338,13.391 0.384,13.478 0.447,13.553 0.522,13.616 0.609,13.662 0.702,13.69 0.793,13.699 0.8,13.699 46.5,13.699 46.559,13.704 46.615,13.722 46.667,13.749 46.713,13.787 46.751,13.833 46.779,13.885 46.796,13.941 46.801,14 46.801,15.999 54.16,15.999 54.219,16.004 54.275,16.021 54.327,16.049 54.373,16.087 54.411,16.133 54.438,16.185 54.456,16.241 54.461,16.3 54.461,24.9 54.456,24.959 54.438,25.015 54.411,25.067 54.373,25.113 54.327,25.151 54.275,25.179 54.219,25.196 54.16,25.201 46.801,25.201 46.801,26.899 80.4,26.899 80.407,26.899
GND on L3-GND (split plane): 80.498,26.89 80.591,26.862 80.678,26.816 80.753,26.753 80.816,26.678 80.862,26.591 80.89,26.498 80.899,26.407 80.899,26.4 80.899,14 80.904,13.941 80.921,13.885 80.949,13.833 80.987,13.787 81.033,13.749 81.085,13.722 81.141,13.704 81.2,13.699 126.9,13.699 126.907,13.699 126.998,13.69 127.091,13.662 127.178,13.616 127.253,13.553 127.316,13.478 127.362,13.391 127.39,13.298 127.399,13.207 127.399,13.2 127.399,0.8 127.399,0.793 127.39,0.703 127.362,0.609 127.316,0.522 127.253,0.447 127.178,0.384 127.091,0.338 126.998,0.31 126.907,0.301 126.9,0.301 0.8,0.301 0.793,0.301 0.702,0.31 0.609,0.338 0.522,0.384 0.447,0.447 0.384,0.522 0.338,0.609 0.31,0.702 0.301,0.793 0.301,0.8 0.301,13.2 0.301,13.207 0.31,13.298 0.338,13.391 0.384,13.478 0.447,13.553 0.522,13.616 0.609,13.662 0.702,13.69 0.793,13.699 0.8,13.699 46.5,13.699 46.559,13.704 46.615,13.722 46.667,13.749 46.713,13.787 46.751,13.833 46.779,13.885 46.796,13.941 46.801,14 46.801,15.999 54.16,15.999 54.219,16.004 54.275,16.021 54.327,16.049 54.373,16.087 54.411,16.133 54.438,16.185 54.456,16.241 54.461,16.3 54.461,24.9 54.456,24.959 54.438,25.015 54.411,25.067 54.373,25.113 54.327,25.151 54.275,25.179 54.219,25.196 54.16,25.201 46.801,25.201 46.801,26.899 80.4,26.899 80.407,26.899

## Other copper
L1-TOP:
  rectangle net GND: 29.5,4.15 30.3,4.45
  rectangle net GND: 67.302,9.075 68.1,9.873
  rectangle net GND: 32.1,11.1 33.425,12.15
  rectangle net GND: 71.4,23.1 73,23.9
  rectangle net GND: 73.6,23.1 75.2,23.9
L4-BOT:
  rectangle net GND: 67.375,9.175 68,9.775
  region net 5V: 80.8,15.6 80.8,13.8 79.9,13.8 77.9,15.8 77.9,16.7 80.762,16.7 80.8,16.662

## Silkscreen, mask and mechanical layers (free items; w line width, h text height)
Top Overlay:
  lines w0.2: 90.285,12.4 90.285,13 ; 90.885,11 91.36,11
  text "1" at 2.575,9.9 h1.2
  text "1" at 115.275,9.425 h1.2
  text "Leap Motion" at 61.2,2 h0.6
  text "0084 - AR Display 2.1" at 61.1,0.8 h0.6
Board Outline:
  the board outline again, w0.2
Sheet Board & Title Block:
  lines w0.152: -34.31,-114.36 -31.77,-111.82 ; -34.31,165.04 -31.77,162.5 ; -31.77,136.846 45.7,136.846 ; -31.77,144.212 45.7,144.212 ; -31.77,151.578 45.7,151.578 ; -31.77,158.69 45.7,158.69 ; 30.333,129.48 30.333,162.5 ; 38.08,129.48 38.08,162.5 ; 283.19,-111.82 283.19,-90.23 308.59,-90.23 394.95,-90.23 ; 283.19,-108.01 308.59,-108.01 ; 283.19,-103.565 308.59,-103.565 ; 283.19,-99.12 308.59,-99.12 342.88,-99.12 ; 283.19,-94.675 308.59,-94.675 342.88,-94.675 ; 297.16,-111.82 297.16,-90.23 ; 308.59,-111.82 308.59,-69.91 394.95,-69.91 ; 308.59,-81.34 394.95,-81.34 ; 311.13,-102.295 340.34,-102.295 ; 317.48,158.69 394.95,158.69 ; 317.48,162.5 317.48,125.5 394.95,125.5 ; 330.18,-90.23 330.18,-81.34 ; 342.88,-111.82 342.88,-90.23 ; 349.23,-90.23 349.23,-81.34 ; 361.295,125.5 361.295,162.5 ; 379.71,-90.23 379.71,-81.34 ; 387.33,125.6 387.33,162.5 ; 394.95,-1.33 397.49,-1.33 ; 397.49,-114.36 394.95,-111.82 ; 397.49,165.04 394.95,162.5 ; -31.77,-111.82 394.95,-111.82 ; -31.77,-111.82 -31.77,162.5 ; -31.77,162.5 394.95,162.5 ; -31.77,162.5 45.7,162.5 45.7,129.48 -31.77,129.48 -31.77,162.5 ; 394.95,-111.82 394.95,162.5
  lines w0.254: -34.31,-114.36 397.49,-114.36 397.49,165.04 -34.31,165.04 -34.31,-114.36
  lines w1.016: 348.595,-94.04 348.595,-108.01 356.215,-108.01 ; 361.295,-101.025 365.105,-101.025 ; 366.375,-108.01 358.755,-108.01 358.755,-94.04 366.375,-94.04 ; 368.915,-108.01 373.995,-94.04 379.075,-108.01 ; 372.725,-102.295 375.265,-102.295 ; 381.615,-108.01 381.615,-94.04 386.695,-94.04 cw(c386.695,-97.106) 388.863,-94.938 cw(c387.965,-95.836) 389.235,-95.836 389.235,-98.594 cw(c387.965,-98.594) 388.863,-99.492 cw(c386.695,-97.324) 386.695,-100.39 381.615,-100.39
  text "Layer / Function" at 327.64,159.96 h1.52
  text "File Name" at 368.915,159.96 h1.52
  text "EXT." at 389.235,159.96 h1.52
  text "ECO Change Description" at -16.53,159.706 h1.52
  text "Date" at 31.476,159.706 h1.52
  text "Rev." at 39.35,159.706 h1.52
  text "Top Solder:" at 344.963,156.15 h1.52
  text ".DwgNo" at 370.566,156.15 h1.52
  text ".GTS" at 388.6,156.15 h1.52
  text "Top Paste:" at 346.487,153.61 h1.52
  text ".DwgNo" at 370.566,153.61 h1.52
  text ".GTP" at 388.6,153.61 h1.52
  text "Top Overlay:" at 343.439,151.07 h1.52
  text ".DwgNo" at 370.566,151.07 h1.52
  text ".GTO" at 388.6,151.07 h1.52
  text ".DwgNo" at 370.566,148.53 h1.52
  text ".GTL" at 388.6,148.53 h1.52
  text "L1(TOP):" at 349.8,148.5 h1.52
  text "8/16/2018" at 31.168,146.928 h0.76
  text "2.1" at 40.012,146.674 h1.52
  text "L2(GND):" at 349.779,146.095 h1.52
  text ".DwgNo" at 370.595,146.085 h1.52
  text ".GP1" at 388.629,146.085 h1.52
  text "L3(GND):" at 349.779,143.695 h1.52
  text ".DwgNo" at 370.595,143.645 h1.52
  text ".GP2" at 388.629,143.645 h1.52
  text "3/18/2018" at 31.168,139.928 h0.76
  text "2.0" at 40.312,139.674 h1.52
  text ".DwgNo" at 370.566,136.81 h1.52
  text ".GBL" at 388.6,136.81 h1.52
  text "L4(BOT):" at 349.8,136.7 h1.52
  text "Bottom Overlay:" at 339.375,134.27 h1.52
  text ".DwgNo" at 370.566,134.27 h1.52
  text ".GBO" at 388.6,134.27 h1.52
  text "7/19/2017" at 30.968,132.528 h0.76
  text "1.0" at 40.112,132.274 h1.52
  text "Bottom Paste:" at 342.423,131.73 h1.52
  text ".DwgNo" at 370.566,131.73 h1.52
  text ".GBP" at 388.6,131.73 h1.52
  text "Bottom Solder:" at 340.899,129.19 h1.52
  text ".DwgNo" at 370.566,129.19 h1.52
  text ".GBS" at 388.6,129.19 h1.52
  text "Mechanical 1 / Board Outline:" at 318.801,126.65 h1.52
  text ".DwgNo" at 370.566,126.65 h1.52
  text ".GM1" at 388.6,126.65 h1.52
  text ".DwgTitle" at 321.29,-77.53 h3.81
  text "SIZE" at 316.21,-83.88 h1.52
  text "CAGE CODE" at 333.355,-83.88 h1.52
  text "DWG NO." at 359.39,-83.88 h1.52
  text "REV." at 384.79,-83.88 h1.52
  text "Tabloid" at 311.13,-88.96 h2.54
  text ".CageCode" at 333.99,-88.96 h2.54
  text ".DwgNo" at 354.31,-88.96 h3.05
  text ".Revision" at 383.52,-88.96 h3.05
  text "APPROVALS" at 285.73,-93.024 h1.02
  text "DATE" at 300.97,-93.024 h1.02
  text "SHEET NO.:" at 309.86,-93.405 h1.52
  text "1" at 327.005,-93.405 h1.52
  text "OF" at 330.815,-93.405 h1.52
  text "1" at 335.895,-93.405 h1.52
  text "ENGINEER:" at 283.825,-95.945 h0.76
  text ".Engineer" at 283.825,-97.85 h0.76
  text "8/16/2018" at 300.335,-97.85 h0.76
  text "SCH NO.:" at 309.86,-97.85 h1.52
  text ".SchNo" at 327.005,-97.85 h1.52
  text "CHECKED BY:" at 283.825,-100.39 h0.76
  text "CONFIDENTIALITY NOTICE" at 314.94,-101.66 h1.02
  text ".CheckedBy" at 283.825,-102.295 h0.76
  text ".CheckedByDate" at 300.335,-102.295 h0.76
  text "This drawing is confidential and contains" at 310.495,-104.2 h0.76
  text "DRAWN BY:" at 283.825,-104.835 h0.76
  text "proprietary information and intellectual" at 310.495,-105.47 h0.76
  text ".DrawnBy" at 283.825,-106.74 h0.76
  text "8/16/2018" at 300.335,-106.74 h0.76
  text "property. Any of the information contained" at 310.495,-106.74 h0.76
  text "herein may not be reproduced or disclosed" at 310.495,-108.01 h0.76
  text "ISSUED:" at 283.825,-109.28 h0.76
  text "without authorization by LEAP Motion." at 310.495,-109.28 h0.76
  text ".Issued" at 283.825,-111.185 h0.76
  text "8/16/2018" at 300.335,-111.185 h0.76
Fabrication Notes:
  lines w0.1: 173.134,91.17 297.3,91.17 ; 173.134,94.98 297.3,94.98 ; 173.134,99.425 297.3,99.425 ; 173.134,103.235 297.3,103.235 ; 173.134,107.045 297.3,107.045 ; 173.134,111.49 297.3,111.4 ; 201.074,87.36 201.074,115.935 ; 224.569,87.36 224.569,115.935 ; 266.479,87.36 266.479,115.935 ; 173.134,115.935 173.134,121.015 297.3,121.015 297.3,115.935 ; 173.134,115.935 297.3,115.935 ; 173.134,115.935 173.134,87.36 297.3,87.36 297.3,115.935
  lines w0.152: 172.827,74.464 391.267,74.464
  text "Impedance Stackup" at 174.632,117.179 h2.54
  text "Layer Name" at 174.632,113.115 h1.52
  text "Copper Weight" at 202.09,113.115 h1.52
  text "Impedance" at 225.864,113.115 h1.52
  text "Trace Width/Space" at 267.393,113.115 h1.52
  text "0.0762mm / 0.0762mm" at 268.5,108.4 h1.52
  text "L1" at 185.339,108.2 h1.52
  text "0.5oz" at 209.339,108.2 h1.52
  text "100 Ohm (+/- 10%)" at 234.339,108.2 h1.52
  text "0.0762mm / 0.0762mm" at 268.5,104.3 h1.52
  text "L4" at 185.339,104.2 h1.52
  text "0.5oz" at 209.339,104.2 h1.52
  text "100 Ohm (+/- 10%)" at 234.339,104.2 h1.52
  text "FABRICATION NOTES" at 172.827,77.004 h2.54
  text "General:" at 175.367,70.654 h1.52
  text "1. Fabricate PCB in accordance with IPC-6012,        ; per IPC-6011." at 185.527,68.114 h1.52
  text ".IPCclass" at 252.837,68.114 h1.52
  text "2. Board assembler shall adjust solder mask and solder stencil to achieve J-STD-001 and IPC-A-610,        , rating." at 185.527,65.574 h1.52
  text ".IPCclass" at 331.577,65.574 h1.52
  text "Materials:" at 175.367,57.954 h1.52
  text "3. Laminate and Prepreg (B-stage) to be in accordance with IPC-4101/99 (RoHS Compliant UL/ANSI FR-4/99)." at 185.527,55.414 h1.52
  text "4. Copper foil to be in accordance with IPC-MF-150.  Unless otherwise specified, all copper weight for inner signal layers and inner plane" at 185.527,52.874 h1.52
  text "layers to be        For outer layers       Copper weight is to be considered 'finished'." at 190.1,50.4 h1.52
  text ".InnerCopperWeight" at 208.9,50.4 h1.52
  text ".OuterCopperWeight" at 245.9,50.3 h1.52
  text "5. Fabricator to adjust dielectric to meet impedance and overall thickness tolerance." at 185.527,47.794 h1.52
  text "Drill Holes and Slots:" at 175.367,40.174 h1.52
  text "6. All hole and slot sizes specified are finished size (after plating)." at 185.527,37.634 h1.52
  text "7. Holes under 7mil shall be within 0.003'' of the specified hole size, unless otherwise specified in the drill table." at 185.527,35.094 h1.52
  text "Finish:" at 175.697,27.592 h1.52
  text "8. Shall be plated with Electroless Nickel Immersion Gold (ENIG) per IPC-4552." at 185.527,24.934 h1.52
  text "9. Apply liquid photo imageable solder mask (color              ).  Via holes covered with solder mask do not need to be plugged." at 185.527,22.394 h1.52
  text ".BoardColor" at 261.346,22.292 h1.52
  text "10. Silkscreen shall be White, permanent, non conductive ink.  There shall be no silkscreen on any solderable component pad." at 185.527,19.854 h1.52
  text "11. Overall board thickness shall be        +/- 10% and is inclusive of all plating and solder mask coatings." at 185.527,17.314 h1.52
  text ".BoardThickness" at 240.6,17.3 h1.52
  text "Marking:" at 174.427,8.898 h1.52
  text "12. UL logo, manufacturer's identification and date code letter shall be  rendered in etch on the bottom side of the board" at 184.282,5.884 h1.52
  text "approximately where shown." at 191.902,3.344 h1.52
  text "Test Requirements:" at 174.122,-4.276 h1.52
  text "13. 100% net list electrical verification using customer supplied IPC-D-356 net list for opens and shorts." at 184.282,-6.816 h1.52
  text "14. No changes shall be made without LEAP Motion's consent, unless stated otherwise." at 184.3,-10 h1.52
Assembly Notes:
  lines w0.152: 172.827,-28.406 391.267,-28.406
  text "ASSEMBLY NOTES" at 172.827,-25.866 h2.54
  text "1.  This drawing is CAD generated.  No changes shall be made without LEAP Motion's consent." at 185.527,-33.486 h1.52
  text "2.  Use only no-clean RoHS compliant solder." at 185.527,-36.026 h1.52
  text "3.  Assemble and solder per J-STD-001, Class 2." at 185.527,-38.566 h1.52
  text "4.  Prior to shipment, each assembly must be packaged seperately in a static shielding bag in a manner that protects from physical damage." at 185.527,-41.106 h1.52
  text "5.  Inspect to IPC-A-610, Class 2." at 185.527,-43.646 h1.52
  text "6.  DFM report is required for all first article builds." at 185.527,-46.186 h1.52
  text "7.  Board revision shall be written/labeled in the space provided on the board." at 185.527,-48.726 h1.52
Drill Drawing:
  text ".LEGEND" at -29.23,-106.105 h1.52
  text "Drill Drawing." at -29.23,-109.28 h1.52

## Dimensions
81.2,26.4 to 127.7,13.2 on Dimensions
0,13.2 to 46.5,27.2 on Dimensions
127.7,14 to 127.7,0 on Dimensions
0,0 to 127.7,0 on Dimensions
81.15,27.2 to 81.15,14 on Dimensions
46.56,27.2 to 46.56,24.9 on Dimensions
46.55,14 to 54.16,16.3 on Dimensions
